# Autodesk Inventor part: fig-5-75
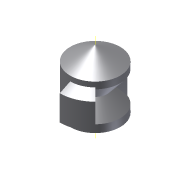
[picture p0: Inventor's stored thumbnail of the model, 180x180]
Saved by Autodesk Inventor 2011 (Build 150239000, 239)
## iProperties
Created: 2004-05
Part Number: fig-5-75
Document SubType Name: Modeling
Designer: CADCIM Technologies
Manufacturer: Standard
Standards Organization: Custom
Density: 1 g/cm^3
Author: CADCIM Technologies
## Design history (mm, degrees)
sketch "Sketch1"
  geometry: L1 (0, -21.51)-(0, 21.51); L2 (0, 21.51)-(-14.639, 13.059); L3 (-14.639, 13.059)-(-14.639, -13.059); L4 (-14.639, -13.059)-(0, -21.51); 2 further points
  constraints: 8 end point, 1 coincident, 1 equal length, 1 midpoint, 1 parallel, 1 vertical, 1 other
  dimensions: "d3" = 120 deg angle of L4 L3
revolve "Revolution1" sketch "Sketch1" stored, may be unused: angle "d0" = 90 deg
workaxis "Work Axis1"
sketch "Sketch2"
  geometry: L1 (-15.658, 10.423)-(-7.144, 0); L2 (-7.144, 0)-(-15.658, -9.738); L3 (-15.658, -9.738)-(-15.658, 10.423); L4 (0, -25.812)-(0, 34.416) reference
  constraints: 6 end point, 1 vertical
revolve "Revolution2" sketch "Sketch2" stored, may be unused: angle "d4" = 140 deg
sketch "Sketch3"
  geometry: L1 (-14.955, 9.983)-(-20.736, 7.191); L2 (-20.736, 7.191)-(-20.736, -7.686); L3 (-20.736, -7.686)-(-15, -10.57); L4 (0, -25.812)-(0, 34.416) reference
  constraints: 6 end point, 1 equal length, 1 vertical
revolve "Revolution4" sketch "Sketch3" stored, may be unused: angle "d9" = 45 deg
body "Solid1"
other parameters: "d11" = 45 deg
